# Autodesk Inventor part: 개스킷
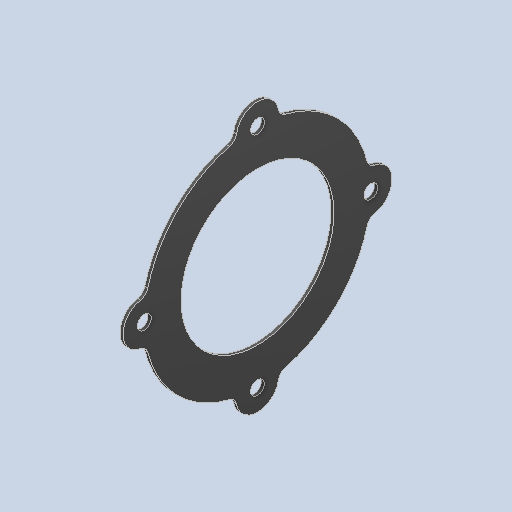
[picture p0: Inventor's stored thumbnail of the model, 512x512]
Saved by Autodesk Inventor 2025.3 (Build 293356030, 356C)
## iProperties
Created: 2025-08
Part Number: 개스킷
Material: 황동, 연질 노란색
Document SubType Name: Modeling
Designer: infra011
Density: 8.47 g/cm^3
Appearance: 기본값
Author: jhkim
Sending System: Autodesk Inventor 2026
Preprocessor: ST-DEVELOPER v20.1
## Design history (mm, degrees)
feature "솔리드2"
node "솔리드1"
